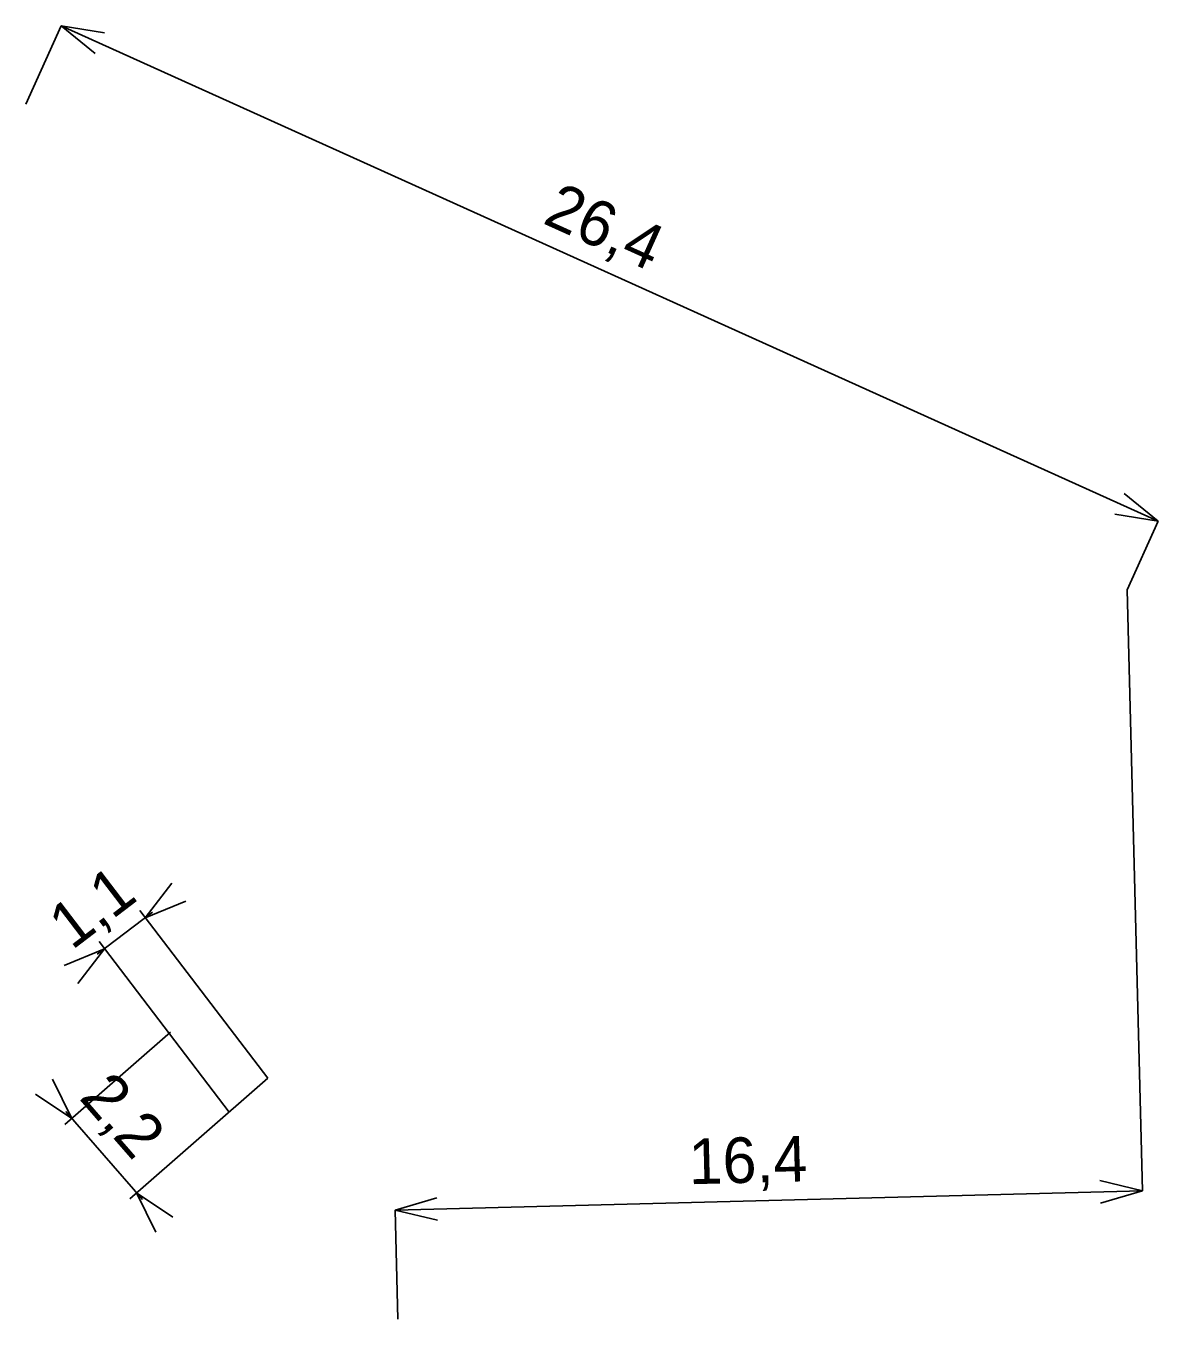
# Model space of a CAD drawing. Extents: x -739737 to -739161, y -1046103 to -1045828.
# Drawn here: x -739185.43 to -739160.57, y -1046103.47 to -1046075.08 of the extents above; entities that cross this region are included whole.
import ezdxf

# ---------------------------------------------------------------- set-up
doc = ezdxf.new("R2010")
doc.units = 0
doc.layers.add('Kota_OPTO', color=7, linetype='Continuous')
doc.layers.add('Kota_VN', color=7, linetype='Continuous')

msp = doc.modelspace()

# ---------------------------------------------------------------- linework, layer by layer
at = {"layer": 'Kota_OPTO'}
for p, q in [((-739182.806, -1046094.656), (-739182.219, -1046093.896)), ((-739183.858, -1046095.459), (-739182.647, -1046094.535)), ((-739180.115, -1046098.18), (-739182.927, -1046094.497)), ((-739182.806, -1046094.656), (-739181.917, -1046094.291)), ((-739183.699, -1046095.338), (-739184.588, -1046095.703)), ((-739183.699, -1046095.338), (-739184.286, -1046096.098)), ((-739180.96, -1046098.924), (-739183.82, -1046095.179)), ((-739182.25, -1046097.172), (-739184.568, -1046099.195)), ((-739184.417, -1046099.064), (-739184.84, -1046098.201)), ((-739180.115, -1046098.18), (-739183.145, -1046100.825)), ((-739184.417, -1046099.064), (-739185.214, -1046098.528)), ((-739184.549, -1046098.913), (-739182.863, -1046100.844)), ((-739182.994, -1046100.694), (-739182.197, -1046101.23)), ((-739182.994, -1046100.694), (-739182.571, -1046101.557))]:
    msp.add_line(p, q, dxfattribs=at)
at = {"layer": 'Kota_VN'}
for p, q in [((-739185.426, -1046076.798), (-739184.65, -1046075.079)), ((-739184.65, -1046075.079), (-739160.569, -1046085.952)), ((-739184.65, -1046075.079), (-739183.702, -1046075.235)), ((-739184.65, -1046075.079), (-739183.907, -1046075.688)), ((-739160.569, -1046085.952), (-739161.312, -1046085.343)), ((-739160.569, -1046085.952), (-739161.517, -1046085.796)), ((-739161.25, -1046087.46), (-739160.569, -1046085.952)), ((-739161.25, -1046087.46), (-739160.912, -1046100.654)), ((-739160.912, -1046100.654), (-739161.846, -1046100.429)), ((-739177.322, -1046101.075), (-739160.912, -1046100.654)), ((-739177.322, -1046101.075), (-739176.401, -1046100.803)), ((-739160.912, -1046100.654), (-739161.833, -1046100.926)), ((-739177.26, -1046103.469), (-739177.322, -1046101.075)), ((-739177.322, -1046101.075), (-739176.388, -1046101.3))]:
    msp.add_line(p, q, dxfattribs=at)

# ---------------------------------------------------------------- texts
at = {"layer": 'Kota_OPTO'}
for s, rotation, p in [('1,1', 37.3665, (-739184.415, -1046095.381)), ('2,2', 311.1217, (-739184.278, -1046098.617))]:
    msp.add_text(s, height=1, rotation=rotation, dxfattribs=at).set_placement(p)
at = {"layer": 'Kota_VN'}
for s, rotation, p in [('26,4', 335.6995, (-739174.106, -1046079.401)), ('16,4', 1.4685, (-739170.863, -1046100.509))]:
    msp.add_text(s, height=1, rotation=rotation, dxfattribs=at).set_placement(p)

doc.saveas('drawing.dxf')
